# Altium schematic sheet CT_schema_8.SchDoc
size 391 x 238 mm
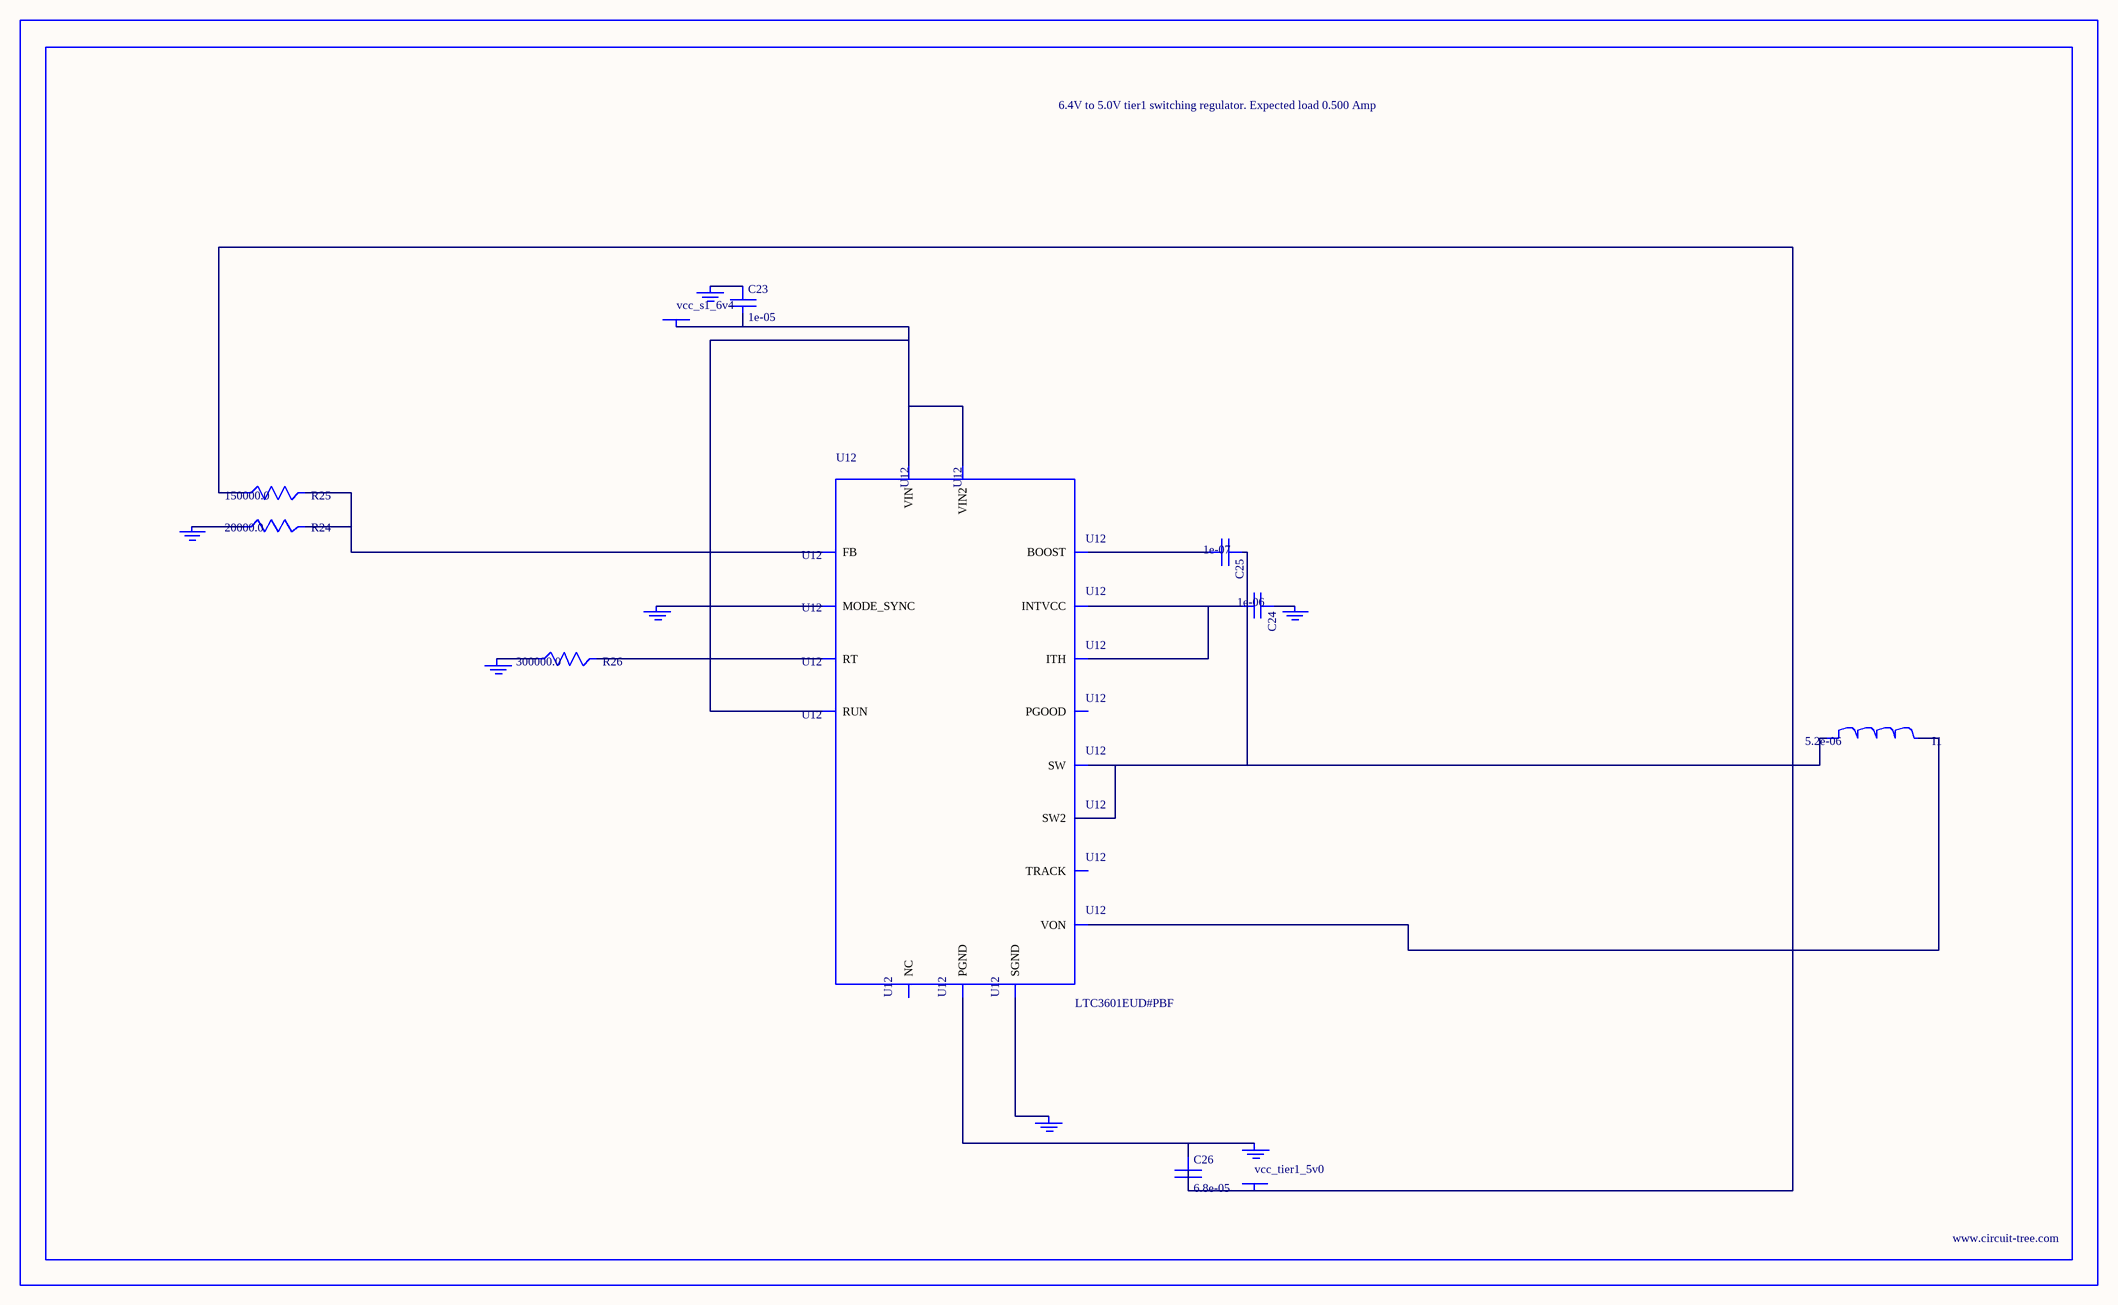
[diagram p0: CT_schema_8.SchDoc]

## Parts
BORDER7  (no value)
C23  1e-05  [C0805]
C24  1e-06  [C0603]
C25  1e-07  [C0402]
C26  6.8e-05  [2220]
GND_INSTANCE_7_0  (no value)
GND_INSTANCE_7_1  (no value)
GND_INSTANCE_7_2  (no value)
GND_INSTANCE_7_3  (no value)
GND_INSTANCE_7_4  (no value)
GND_INSTANCE_7_5  (no value)
GND_INSTANCE_7_6  (no value)
I1  5.2e-06  [DR1040]
POWER_INSTANCE_7_0  vcc_s1_6v4
POWER_INSTANCE_7_1  vcc_tier1_5v0
R24  20000.0  [R0603]
R25  150000.0  [R0603]
R26  300000.0  [R0603]
U12  LTC3601EUD#PBF  [QFN-16_EP]

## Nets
NetC23_1: C23.1 GND_INSTANCE_7_5.0(GND)
NetC23_2: C23.2 POWER_INSTANCE_7_0.0(PWR) U12.14(RUN) U12.15(VIN) U12.16(VIN2)
NetC24_1: C24.1 GND_INSTANCE_7_1.0(GND)
NetC24_2: C24.2 U12.7(INTVCC) U12.12(ITH)
NetC25_1: C25.1 I1.1 U12.3(SW) U12.4(SW2)
NetC25_2: C25.2 U12.6(BOOST)
NetC26_1: C26.1 GND_INSTANCE_7_6.0(GND) U12.17(PGND)
NetC26_2: C26.2 I1.2 POWER_INSTANCE_7_1.0(PWR) R25.1 U12.8(VON)
NetGND_INSTANCE_7_0_0: GND_INSTANCE_7_0.0(GND) U12.1(MODE_SYNC)
NetGND_INSTANCE_7_2_0: GND_INSTANCE_7_2.0(GND) U12.9(SGND)
NetGND_INSTANCE_7_3_0: GND_INSTANCE_7_3.0(GND) R26.1
NetGND_INSTANCE_7_4_0: GND_INSTANCE_7_4.0(GND) R24.1
NetR24_2: R24.2 R25.2 U12.11(FB)
NetR26_2: R26.2 U12.10(RT)

Not connected (* = marked no-connect by the designer): U12 2(PGOOD) 5(NC) 13(TRACK)

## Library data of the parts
BORDER7 = BORDER_PAGE7
C23 = C0805C106K8RACTU
C24 = C0603C105K3RACTU
C25 = C0402C104K3RACTU
C26 = C5750X5R1A686M
GND_INSTANCE_7_0-GND_INSTANCE_7_6 = GND
I1 = DR1040-5R2-R
POWER_INSTANCE_7_0 POWER_INSTANCE_7_1 = PWR
R24 = RC0603JR-0720KL
R25 = RC0603JR-07150KL
R26 = RC0603JR-07300KL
